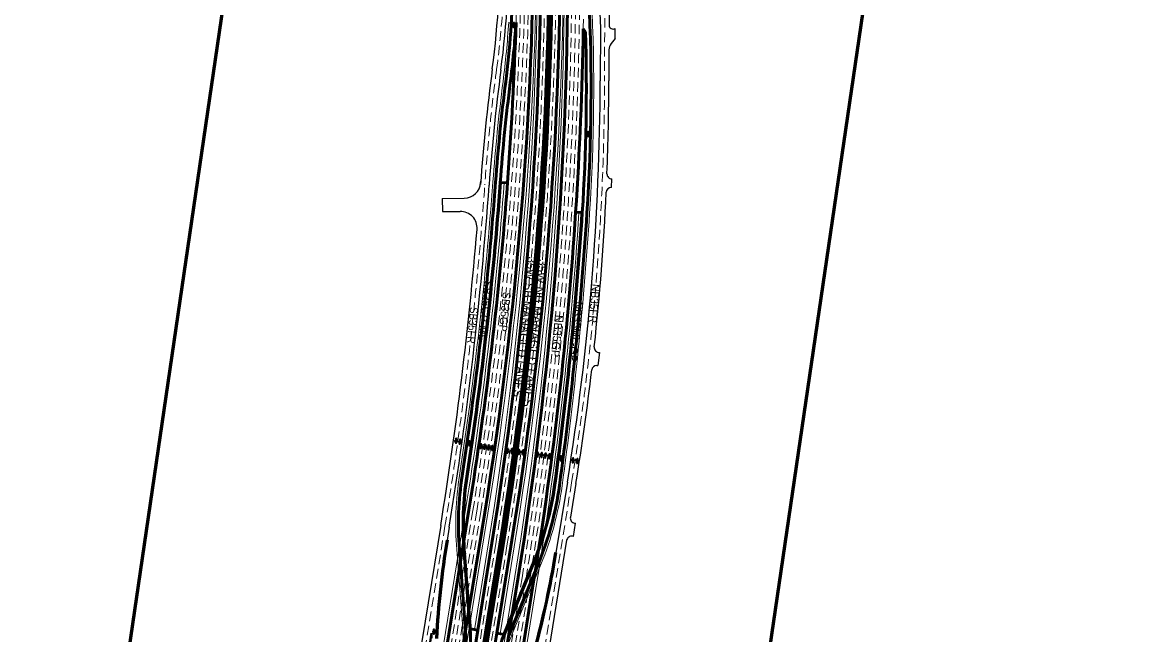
# Model space of a CAD drawing. Extents: x 2329387 to 2347382, y 6951580 to 6987999.
# Drawn here: x 2331839 to 2335155, y 6982469 to 6984307 of the extents above; entities that cross this region are included whole.
import ezdxf

# ---------------------------------------------------------------- set-up
doc = ezdxf.new("R2010")
doc.units = 0
doc.header["$LTSCALE"] = 9.6
doc.linetypes.add('MEDIUM_DASHED', pattern=[4.5, 3, -1.5])
for name, color, linetype, lineweight in [('26', 7, 'Continuous', 53), ('27', 7, 'Continuous', 40), ('28', 7, 'Continuous', 25), ('30', 7, 'Continuous', 13), ('31', 7, 'Continuous', 53), ('41', 7, 'Continuous', 35), ('50', 7, 'MEDIUM_DASHED', 13), ('62', 7, 'Continuous', 60)]:
    doc.layers.add(name, color=color, linetype=linetype, lineweight=lineweight)
doc.layers.add('40', color=7, linetype='Continuous')

msp = doc.modelspace()

# ---------------------------------------------------------------- linework, layer by layer
at = {"layer": '26'}
for p, q in [((2333226.175, 6982836.253), (2332841.664, 6980470.76)), ((2333178.797, 6982843.954), (2332976.382, 6981598.707)), ((2333326.427, 6982642.749), (2332969.98, 6980449.902)), ((2333373.805, 6982635.048), (2333212.588, 6981643.246))]:
    msp.add_line(p, q, dxfattribs=at)
at = {"layer": '26', "lineweight": 13}
for p, q in [((2333236.045, 6982834.649), (2332851.535, 6980469.155)), ((2333168.926, 6982845.559), (2332966.511, 6981600.312)), ((2333316.556, 6982644.353), (2332960.11, 6980451.507)), ((2333383.672, 6982633.418), (2333222.458, 6981641.641))]:
    msp.add_line(p, q, dxfattribs=at)
at = {"layer": '26'}
for centre, radius, end in [((2321965.812, 6984666.623), 11408.156, 359.86208), ((2321965.386, 6984489.484), 11510.156, 359.86208), ((2321965.812, 6984666.623), 11360.156, 355.75018), ((2321965.386, 6984489.484), 11558.156, 356.26828)]:
    msp.add_arc(centre, radius, 350.76734, end, dxfattribs=at)
at = {"layer": '26', "lineweight": 13}
for centre, radius, start, end in [((2321965.812, 6984666.623), 11418.156, 350.76734, 359.86208), ((2321965.386, 6984489.484), 11500.156, 350.76734, 359.86208), ((2321965.812, 6984666.623), 11350.156, 350.76734, 355.74972), ((2321965.386, 6984489.484), 11568.156, 350.76721, 356.26823)]:
    msp.add_arc(centre, radius, start, end, dxfattribs=at)
at = {"layer": '27', "lineweight": 25}
for p, q in [((2333112.448, 6982753.646), (2333116.396, 6982753.004)), ((2333436.673, 6982716.404), (2333440.621, 6982715.762))]:
    msp.add_line(p, q, dxfattribs=at)
at = {"layer": '27'}
msp.add_line((2333067.062, 6982474.436), (2333016.95, 6982166.149), dxfattribs=at)
for centre, radius, start, end in [((2335926.305, 6982296.254), 2850.789, 170.76734, 176.73017), ((2330626.764, 6983173.154), 2850.789, 344.8045, 350.76734), ((2335926.305, 6982296.254), 2864.789, 176.43406, 176.73018)]:
    msp.add_arc(centre, radius, start, end, dxfattribs=at)
at = {"layer": '27', "lineweight": 25}
for centre, start, end in [((2335926.305, 6982296.254), 170.76734, 176.73017), ((2330626.764, 6983173.154), 344.8045, 350.76734)]:
    msp.add_arc(centre, 2846.789, start, end, dxfattribs=at)
at = {"layer": '28'}
for p, q in [((2333561.815, 6984589.026), (2333573.093, 6984288.998)), ((2333599.599, 6984499.54), (2333599.115, 6984298.207)), ((2333573.093, 6984288.998), (2333572.713, 6984131.254)), ((2333617.124, 6984257.58), (2333617.197, 6984287.834)), ((2333617.124, 6984257.58), (2333605.323, 6984242.521)), ((2333598.936, 6984224.089), (2333598.713, 6984131.192)), ((2333606.739, 6983810.898), (2333605.97, 6983810.919)), ((2333606.74, 6983810.921), (2333607.725, 6983836.719)), ((2333099.057, 6983778.186), (2333099.567, 6983738.857)), ((2333099.058, 6983778.186), (2333164.765, 6983778.997)), ((2333099.567, 6983738.857), (2333152.689, 6983739.546)), ((2333570.13, 6983316.456), (2333565.689, 6983277.342)), ((2333562.078, 6983277.326), (2333565.689, 6983277.342)), ((2333474.09, 6982927.893), (2333439.634, 6982715.922)), ((2333499.753, 6982923.721), (2333483.229, 6982822.07)), ((2333094.181, 6982797.091), (2332786.266, 6980902.809)), ((2333119.845, 6982792.92), (2333113.435, 6982753.486)), ((2333492.168, 6982764.874), (2333498.59, 6982804.378)), ((2333495.634, 6982804.857), (2333498.59, 6982804.378)), ((2333471.999, 6982752.984), (2333182.352, 6980971.084)), ((2333492.168, 6982764.874), (2333489.354, 6982765.36))]:
    msp.add_line(p, q, dxfattribs=at)
for centre, radius, start, end in [((2330410.097, 6984543.948), 2863.789, 352.43248, 0.729), ((2330410.097, 6984543.948), 2889.789, 352.43248, 0.729), ((2333611.115, 6984298.178), 12, 179.86208, 300.45354), ((2333628.936, 6984224.017), 30, 141.91627, 179.86208), ((2338929.61, 6983412.117), 5730.578, 172.43248, 175.91866), ((2338929.61, 6983412.117), 5704.578, 172.43248, 175.91866), ((2325958.298, 6984149.583), 7614.437, 350.76734, 359.86208), ((2325958.298, 6984149.583), 7640.437, 357.77012, 359.86208), ((2333607.938, 6983851.718), 15, 177.77012, 269.18606), ((2321784.467, 6984635.483), 11484.156, 350.76734, 355.91866), ((2333164.099, 6983828.993), 50, 270.7623, 356.00018), ((2321782.733, 6984624.819), 11459.156, 356.00018, 356.02554), ((2333605.562, 6983795.924), 15, 88.43902, 177.35216), ((2325958.298, 6984149.583), 7640.437, 353.86514, 357.35216), ((2333153.338, 6983689.55), 50, 355.24373, 90.74293), ((2321784.467, 6984635.483), 11458.156, 350.76733, 355.24373), ((2333569.893, 6983331.454), 15, 173.86514, 270.90516), ((2325958.298, 6984149.583), 7640.437, 350.76734, 353.34452), ((2333562.145, 6983262.326), 15, 90.25451, 173.34452), ((2333498.035, 6982819.664), 15, 170.76734, 260.78809), ((2333486.805, 6982750.578), 15, 80.21622, 170.76734)]:
    msp.add_arc(centre, radius, start, end, dxfattribs=at)
at = {"layer": '30', "lineweight": 53}
for p, q in [((2333271.366, 6982740.303), (2332900.887, 6980461.133)), ((2333281.236, 6982738.699), (2332910.757, 6980459.529)), ((2333247.677, 6982744.154), (2333205.301, 6982483.463)), ((2333304.925, 6982734.848), (2333262.55, 6982474.157))]:
    msp.add_line(p, q, dxfattribs=at)
at = {"layer": '30'}
for p, q in [((2333275.314, 6982739.661), (2332904.835, 6980460.492)), ((2333277.288, 6982739.341), (2332906.809, 6980460.171)), ((2333237.806, 6982745.758), (2333195.431, 6982485.067)), ((2333314.796, 6982733.244), (2333272.42, 6982472.553))]:
    msp.add_line(p, q, dxfattribs=at)
for radius in [11420.156, 11458.156, 11460.156, 11498.156]:
    msp.add_arc((2321965.599, 6984578.053), radius, 350.76734, 359.86208, dxfattribs=at)
at = {"layer": '30', "lineweight": 53}
for radius in [11430.156, 11454.156, 11464.156, 11488.156]:
    msp.add_arc((2321965.599, 6984578.053), radius, 350.76734, 359.86208, dxfattribs=at)
at = {"layer": '31'}
for p, q in [((2333521.765, 6984286.849), (2333528.597, 6984277.405)), ((2333294.732, 6983824.774), (2333272.778, 6983826.207)), ((2333518.991, 6983735.901), (2333499.035, 6983737.223)), ((2333150.159, 6982725.738), (2333167.815, 6982494.491)), ((2333164.119, 6982726.803), (2333181.774, 6982495.557)), ((2333286.288, 6982474.77), (2333374.564, 6982689.337)), ((2333299.235, 6982469.444), (2333387.509, 6982684.005)), ((2333205.301, 6982483.463), (2333180.043, 6982328.074)), ((2333205.301, 6982483.463), (2333182.565, 6982487.159)), ((2333262.55, 6982474.157), (2333237.926, 6982322.673)), ((2333262.55, 6982474.157), (2333284.574, 6982470.577))]:
    msp.add_line(p, q, dxfattribs=at)
at = {"layer": '31', "lineweight": 13}
for p, q in [((2333142.183, 6982725.129), (2333159.191, 6982502.364)), ((2333168.107, 6982727.108), (2333185.763, 6982495.862)), ((2333282.589, 6982476.292), (2333370.862, 6982690.853)), ((2333309.983, 6982474.542), (2333394.907, 6982680.961))]:
    msp.add_line(p, q, dxfattribs=at)
at = {"layer": '31'}
for centre, radius, start, end in [((2330447.34, 6984489.989), 2864.789, 352.73094, 358.80695), ((2327815.533, 6984107.908), 5729.578, 356.26817, 2.69062), ((2321965.812, 6984666.623), 11360.156, 355.75018, 358.18076), ((2330447.34, 6984489.989), 2878.789, 352.73094, 356.33518), ((2321965.386, 6984489.484), 11558.156, 356.26828, 358.99546), ((2327815.533, 6984107.908), 5715.578, 356.26817, 1.69937), ((2338972.633, 6983402.553), 5729.578, 172.73094, 175.74918), ((2338972.633, 6983402.553), 5715.578, 172.73094, 175.74918), ((2321965.812, 6984666.623), 11324.156, 351.26388, 355.74918), ((2321965.812, 6984666.623), 11338.156, 351.26388, 355.74918), ((2321965.386, 6984489.484), 11578.156, 352.20807, 356.26817), ((2321965.386, 6984489.484), 11592.156, 352.20807, 356.26817), ((2334116.277, 6982799.5), 968.93, 171.26388, 184.36603), ((2334116.277, 6982799.5), 954.93, 171.26388, 184.36603), ((2332504.398, 6983047.33), 940.93, 337.63695, 352.20807), ((2332504.398, 6983047.33), 954.93, 337.63695, 352.20807), ((2332215.656, 6982421.795), 954.93, 350.76734, 4.36603), ((2332215.656, 6982421.795), 968.93, 354.44931, 4.36603), ((2334182.346, 6982106.118), 968.93, 157.63695, 167.08536)]:
    msp.add_arc(centre, radius, start, end, dxfattribs=at)
at = {"layer": '31', "lineweight": 13}
for centre, radius, start, end in [((2327815.533, 6984107.908), 5737.578, 356.26817, 2.69062), ((2330447.34, 6984489.989), 2856.789, 352.73094, 356.32808), ((2338972.633, 6983402.553), 5737.578, 172.73094, 175.74918), ((2321965.812, 6984666.623), 11316.156, 351.26388, 355.74918), ((2321965.812, 6984666.623), 11342.156, 351.26388, 355.74918), ((2321965.386, 6984489.484), 11574.156, 352.20807, 356.26817), ((2321965.386, 6984489.484), 11600.156, 352.20807, 356.26817), ((2334182.346, 6982106.118), 972.93, 157.63695, 157.63695), ((2334116.277, 6982799.5), 976.93, 171.26388, 184.36603), ((2334116.277, 6982799.5), 950.93, 171.26388, 184.36603), ((2332504.398, 6983047.33), 936.93, 337.63695, 352.20807), ((2332504.398, 6983047.33), 962.93, 337.63695, 352.20807), ((2332215.009, 6982430.276), 946.93, 350.76734, 4.36603), ((2332215.656, 6982421.795), 972.93, 3.81511, 4.36603), ((2334185.695, 6982114.26), 946.93, 157.63695, 170.76734), ((2334182.346, 6982106.118), 972.93, 157.63696, 157.9586)]:
    msp.add_arc(centre, radius, start, end, dxfattribs=at)
at = {"layer": '41'}
for points in [[(2333315.341, 6984304.533), (2333312.34, 6984304.554), (2333312.293, 6984297.747), (2333309.856, 6984297.764), (2333313.584, 6984290.538), (2333317.413, 6984297.712), (2333315.294, 6984297.726)], [(2333534.578, 6983964.561), (2333537.578, 6983964.487), (2333537.746, 6983971.291), (2333540.183, 6983971.231), (2333536.583, 6983978.522), (2333532.627, 6983971.418), (2333534.746, 6983971.365)], [(2333142.682, 6983057.552), (2333139.708, 6983057.955), (2333138.794, 6983051.21), (2333136.379, 6983051.538), (2333139.156, 6983043.895), (2333143.868, 6983050.522), (2333141.767, 6983050.807)], [(2333154.464, 6983055.006), (2333151.49, 6983055.409), (2333150.576, 6983048.664), (2333148.16, 6983048.991), (2333150.937, 6983041.349), (2333155.649, 6983047.976), (2333153.549, 6983048.261)], [(2333183.043, 6983049.916), (2333180.069, 6983050.319), (2333179.155, 6983043.574), (2333176.74, 6983043.901), (2333179.517, 6983036.259), (2333184.229, 6983042.886), (2333182.128, 6983043.171)], [(2333216.821, 6983041.622), (2333213.848, 6983042.025), (2333212.933, 6983035.28), (2333210.518, 6983035.607), (2333213.295, 6983027.965), (2333218.007, 6983034.592), (2333215.907, 6983034.877)], [(2333228.125, 6983039.871), (2333225.152, 6983040.274), (2333224.237, 6983033.529), (2333221.822, 6983033.857), (2333224.599, 6983026.214), (2333229.311, 6983032.841), (2333227.211, 6983033.126)], [(2333240.385, 6983037.802), (2333237.411, 6983038.205), (2333236.496, 6983031.46), (2333234.081, 6983031.788), (2333236.858, 6983024.145), (2333241.57, 6983030.772), (2333239.47, 6983031.057)], [(2333252.007, 6983035.892), (2333249.033, 6983036.295), (2333248.119, 6983029.55), (2333245.704, 6983029.878), (2333248.481, 6983022.235), (2333253.193, 6983028.862), (2333251.092, 6983029.147)], [(2333296.705, 6983027.591), (2333293.732, 6983027.994), (2333292.817, 6983021.249), (2333290.402, 6983021.576), (2333293.179, 6983013.934), (2333297.891, 6983020.561), (2333295.791, 6983020.846)], [(2333310.55, 6983026.937), (2333307.576, 6983027.341), (2333306.662, 6983020.596), (2333304.247, 6983020.923), (2333307.024, 6983013.28), (2333311.736, 6983019.908), (2333309.635, 6983020.192)], [(2333326.412, 6983011.726), (2333329.386, 6983011.323), (2333330.3, 6983018.068), (2333332.716, 6983017.741), (2333329.938, 6983025.383), (2333325.227, 6983018.756), (2333327.327, 6983018.471)], [(2333339.255, 6983010.398), (2333342.229, 6983009.995), (2333343.143, 6983016.74), (2333345.559, 6983016.413), (2333342.781, 6983024.055), (2333338.069, 6983017.428), (2333340.17, 6983017.143)], [(2333382.213, 6983004.2), (2333385.186, 6983003.797), (2333386.101, 6983010.542), (2333388.516, 6983010.215), (2333385.739, 6983017.857), (2333381.027, 6983011.23), (2333383.127, 6983010.945)], [(2333394.301, 6983002.465), (2333397.275, 6983002.062), (2333398.189, 6983008.807), (2333400.605, 6983008.479), (2333397.827, 6983016.122), (2333393.115, 6983009.495), (2333395.216, 6983009.21)], [(2333405.956, 6983000.916), (2333408.929, 6983000.513), (2333409.844, 6983007.258), (2333412.259, 6983006.93), (2333409.482, 6983014.573), (2333404.77, 6983007.946), (2333406.87, 6983007.661)], [(2333417.858, 6982999.119), (2333420.832, 6982998.716), (2333421.746, 6983005.461), (2333424.161, 6983005.133), (2333421.384, 6983012.776), (2333416.672, 6983006.148), (2333418.773, 6983005.864)], [(2333452.067, 6982992.596), (2333455.041, 6982992.193), (2333455.955, 6982998.938), (2333458.371, 6982998.61), (2333455.594, 6983006.253), (2333450.882, 6982999.626), (2333452.982, 6982999.341)], [(2333488.355, 6982986.85), (2333491.329, 6982986.447), (2333492.243, 6982993.192), (2333494.659, 6982992.865), (2333491.882, 6983000.507), (2333487.17, 6982993.88), (2333489.27, 6982993.595)], [(2333501.265, 6982984.311), (2333504.239, 6982983.908), (2333505.153, 6982990.653), (2333507.568, 6982990.326), (2333504.791, 6982997.968), (2333500.079, 6982991.341), (2333502.18, 6982991.056)], [(2333075.99, 6982485.893), (2333072.991, 6982485.996), (2333072.758, 6982479.193), (2333070.322, 6982479.276), (2333073.852, 6982471.951), (2333077.875, 6982479.018), (2333075.757, 6982479.09)]]:
    msp.add_lwpolyline(points, close=True, dxfattribs=at)
at = {"layer": '50'}
for p, q in [((2333588.557, 6985312.86), (2333585.713, 6984131.223)), ((2333486.921, 6982925.807), (2333169.52, 6980973.17)), ((2333190.641, 6982842.029), (2332806.131, 6980476.536)), ((2333202.486, 6982840.104), (2332817.975, 6980474.611)), ((2333214.33, 6982838.178), (2332829.82, 6980472.685)), ((2333107.013, 6982795.006), (2332799.098, 6980900.723)), ((2333259.521, 6982742.229), (2332889.042, 6980463.059)), ((2333293.081, 6982736.773), (2332922.602, 6980457.604)), ((2333338.271, 6982640.824), (2332981.825, 6980447.977)), ((2333350.116, 6982638.898), (2332993.669, 6980446.052)), ((2333361.961, 6982636.973), (2333005.514, 6980444.126))]:
    msp.add_line(p, q, dxfattribs=at)
for centre, radius, start, end in [((2321965.812, 6984666.623), 11372.156, 350.76734, 359.86208), ((2321965.812, 6984666.623), 11384.156, 350.76734, 359.86208), ((2321965.812, 6984666.623), 11396.156, 350.76734, 359.86208), ((2321965.812, 6984666.623), 11360.156, 358.18076, 359.86208), ((2330410.097, 6984543.948), 2876.789, 352.43248, 0.729), ((2321965.599, 6984578.053), 11442.156, 350.76734, 359.86208), ((2321965.599, 6984578.053), 11476.156, 350.76734, 359.86208), ((2321965.386, 6984489.484), 11522.156, 350.76734, 359.86208), ((2321965.386, 6984489.484), 11534.156, 350.76734, 359.86208), ((2321965.386, 6984489.484), 11546.156, 350.76734, 359.86208), ((2321965.386, 6984489.484), 11558.156, 358.99546, 359.86208), ((2338929.61, 6983412.117), 5717.578, 172.43248, 175.91866), ((2325958.298, 6984149.583), 7627.437, 350.76734, 359.86208), ((2321784.467, 6984635.483), 11471.156, 350.76734, 355.91866)]:
    msp.add_arc(centre, radius, start, end, dxfattribs=at)
at = {"layer": '62'}
msp.add_lwpolyline([(2334855.87, 6987723.712), (2333675.66, 6979665.287), (2331838.812, 6980234.901), (2332975.924, 6987999.043)], close=True, dxfattribs=at)

# ---------------------------------------------------------------- texts
at = {"layer": '40'}
for s, rotation, width, p in [('35W SB MANAGED LANES', 264.154, 1.05, (2333355.757, 6983604.516)), ('35W NB MANAGED LANES', 263.91, 1.1, (2333389.395, 6983597.305)), ('NB35FR', 264.862, 0.95, (2333548.014, 6983522.619)), ('SB35GP', 264.009, 0.95, (2333280.95, 6983498.221)), ('SB35FR', 264.862, 0.9, (2333182.695, 6983453.118))]:
    msp.add_text(s, height=24, rotation=rotation, dxfattribs=dict(at, width=width)).set_placement(p)
for s, rotation, p in [('SB35GP-ML', 264.087, (2333225.433, 6983533.34)), ('NB35ML-GP', 264.108, (2333496.805, 6983470.422)), ('NB35GP', 264.862, (2333436.884, 6983429.913))]:
    msp.add_text(s, height=24, rotation=rotation, dxfattribs=at).set_placement(p)

doc.saveas('drawing.dxf')
